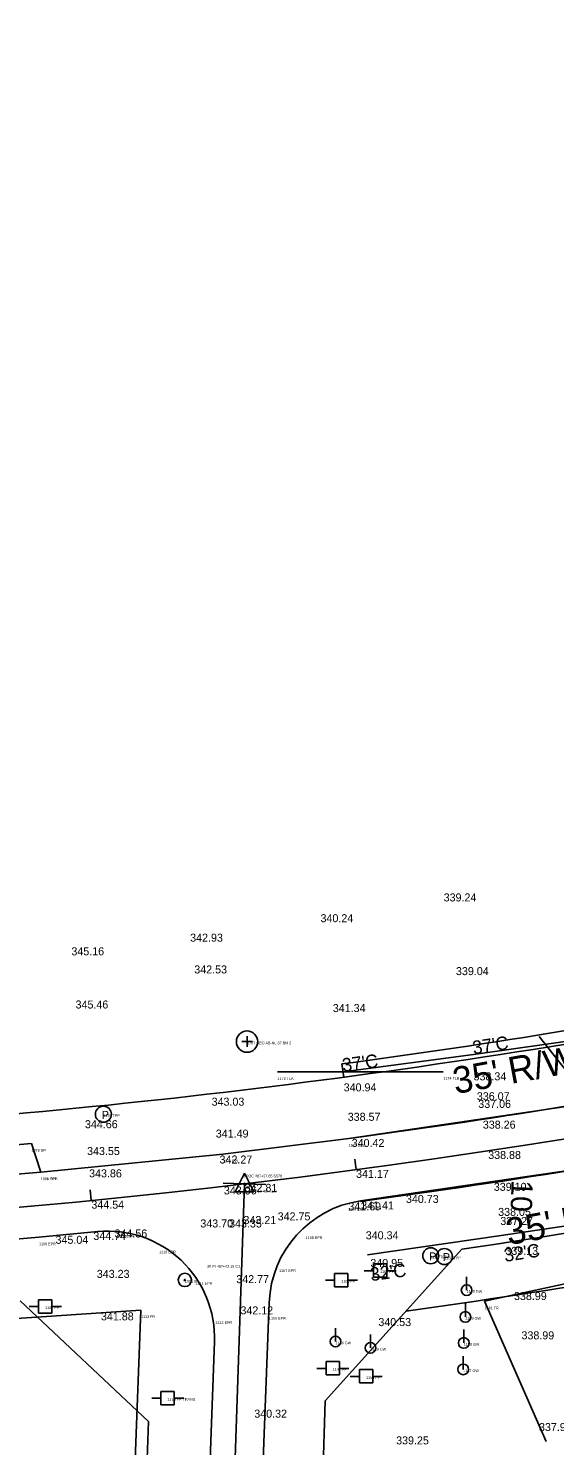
# Model space of a CAD drawing. Extents: x 49683 to 58852, y 49525 to 54803.
# Drawn here: x 50899 to 51097, y 49882 to 50413 of the extents above; entities that cross this region are included whole.
import ezdxf

# ---------------------------------------------------------------- set-up
doc = ezdxf.new("R2010")
doc.units = 0
for name, color, linetype in [('Level 1', 7, 'Continuous'), ('Level 11', 7, 'Continuous'), ('Level 12', 7, 'Continuous'), ('Level 13', 7, 'Continuous'), ('Level 18', 7, 'Continuous'), ('Level 20', 7, 'Continuous'), ('Level 21', 7, 'Continuous'), ('Level 25', 7, 'Continuous'), ('Level 3', 7, 'Continuous'), ('Level 32', 7, 'Continuous'), ('Level 33', 7, 'Continuous'), ('Level 34', 7, 'Continuous'), ('Level 48', 7, 'Continuous'), ('Level 51', 7, 'Continuous'), ('Level 53', 7, 'Continuous'), ('Level 58', 7, 'Continuous'), ('Level 59', 7, 'Continuous'), ('Level 61', 7, 'Continuous'), ('Level 62', 7, 'Continuous'), ('Level 8', 7, 'Continuous'), ('Level 9', 7, 'Continuous')]:
    doc.layers.add(name, color=color, linetype=linetype)

# ---------------------------------------------------------------- blocks, each defined once
blk = doc.blocks.new('PI')
at = {"layer": 'Level 1'}
for p, q in [((0, 4), (-3.5, -3)), ((0, 4), (3.5, -3)), ((-3.5, -3), (3.5, -3))]:
    blk.add_line(p, q, dxfattribs=at)
blk.add_circle((0, 0), 0.25, dxfattribs=at)
blk = doc.blocks.new('PP')
at = {"layer": 'Level 9'}
for p, q in [((2.53, 2.45), (-2.47, 2.45)), ((-2.47, 2.45), (-2.47, -2.55)), ((2.53, -2.55), (2.53, 2.45)), ((-5.91, -0.11), (-2.44, -0.11)), ((-2.47, -2.55), (2.53, -2.55)), ((2.45, -0.11), (6.09, -0.11))]:
    blk.add_line(p, q, dxfattribs=at)
blk = doc.blocks.new('GW')
at = {"layer": 'Level 9'}
blk.add_line((0, 0), (0, 5), dxfattribs=at)
blk.add_circle((0, 0), 2, dxfattribs=at)
blk = doc.blocks.new('TPP')
at = {"layer": 'Level 9'}
blk.add_circle((0, 0), 3, dxfattribs=at)
blk.add_text('P', height=3, dxfattribs=at).set_placement((-0.59, -1.73))
blk = doc.blocks.new('IP')
at = {"layer": 'Level 12'}
for radius in [2.5, 0.25]:
    blk.add_circle((0, 0), radius, dxfattribs=at)
blk = doc.blocks.new('GEO')
at = {"layer": 'Level 12'}
for p, q in [((2, 0), (-2, 0)), ((0, -2), (0, 2))]:
    blk.add_line(p, q, dxfattribs=at)
blk.add_circle((0, 0), 4, dxfattribs=at)

msp = doc.modelspace()

# ---------------------------------------------------------------- linework, layer by layer
at = {"layer": 'Level 1'}
for p, q in [((51022.26, 49985.1), (51021.73, 49989.07)), ((50922.94, 49973.54), (50922.55, 49977.52)), ((50980.44, 49979.81), (50970.24, 49679.98)), ((50972.45, 49980.08), (50980.44, 49979.81)), ((50980.44, 49979.81), (50988.44, 49979.53))]:
    msp.add_line(p, q, dxfattribs=at)
msp.add_arc((50641.56, 52824.47), 2864.78, 268.37962, 311.63333, dxfattribs=at)
at = {"layer": 'Level 11'}
for p, q in [((50992.78, 50021.8), (51054.93, 50021.86)), ((51070.44, 49935.78), (51197.3, 49963.31)), ((51093.47, 49883.18), (51070.44, 49935.78))]:
    msp.add_line(p, q, dxfattribs=at)
at = {"layer": 'Level 13'}
for p, q in [((51061.93, 49955.32), (51010.7, 49898.53)), ((50944.39, 49890.76), (50896.33, 49935.91)), ((51003.22, 49678.86), (51010.7, 49898.53)), ((50938.94, 49730.56), (50944.39, 49890.76))]:
    msp.add_line(p, q, dxfattribs=at)
for radius, start in [(2829.79, 274.71289), (2899.79, 278.33537)]:
    msp.add_arc((50641.55, 52824.48), radius, start, 282.71776, dxfattribs=at)
at = {"layer": 'Level 18'}
for p, q in [((51066.27, 50028.35), (51115.16, 50035.22)), ((51017.34, 50021.8), (51066.27, 50028.35)), ((51076.58, 49960.44), (51126.61, 49967.81)), ((51026.53, 49953.25), (51076.58, 49960.44))]:
    msp.add_line(p, q, dxfattribs=at)
at = {"layer": 'Level 20'}
for radius in [2852.79, 2876.79]:
    msp.add_arc((50641.56, 52824.48), radius, 277.63669, 284.5124, dxfattribs=at)
at = {"layer": 'Level 3'}
for p, q in [((51019.47, 49996.76), (51109.95, 50010.17)), ((50972.31, 49990.88), (51019.47, 49996.76)), ((50904, 49984.2), (50972.31, 49990.88)), ((50834.92, 49978.18), (50904, 49984.2)), ((51023.87, 49973.41), (51114.81, 49986.7)), ((50903.34, 49959.81), (50925.36, 49961.9)), ((50836.42, 49953.95), (50903.34, 49959.81)), ((50985.31, 49820.35), (50989.68, 49935.35)), ((50969.12, 49920.58), (50965.38, 49820.53))]:
    msp.add_line(p, q, dxfattribs=at)
for centre, start, end in [((51029.65, 49933.83), 98.3136, 177.8243), ((50929.15, 49922.08), 357.8573, 95.4304)]:
    msp.add_arc(centre, 40, start, end, dxfattribs=at)
at = {"layer": 'Level 33'}
msp.add_line((51016.95, 50024.75), (51017.61, 50019.79), dxfattribs=at)
for centre, radius, start, end in [((50641.56, 52824.47), 2824.78, 277.63672, 284.51288), ((50641.56, 52824.48), 2919.79, 277.86343, 284.5124)]:
    msp.add_arc(centre, radius, start, end, dxfattribs=at)
at = {"layer": 'Level 34'}
msp.add_line((51090.91, 50035.07), (51104.54, 50017.8), dxfattribs=at)
at = {"layer": 'Level 8'}
for p, q in [((50875.83, 49992.8), (50900.54, 49994.88)), ((50900.54, 49994.88), (50904, 49984.2)), ((50747.24, 49919.1), (50941.57, 49932.52)), ((50941.57, 49932.52), (50934.14, 49742.39))]:
    msp.add_line(p, q, dxfattribs=at)

# ---------------------------------------------------------------- block references
at = {"layer": 'Level 1'}
msp.add_blockref('PI', (50980.44, 49979.81), dxfattribs=at)
at = {"layer": 'Level 12'}
for name, p in [('GEO', (50981.38, 50033.12)), ('IP', (50958.03, 49943.78))]:
    msp.add_blockref(name, p, dxfattribs=at)
at = {"layer": 'Level 9'}
for name, p in [('TPP', (50927.48, 50005.9)), ('TPP', (51050.24, 49952.85)), ('TPP', (51055.37, 49952.58)), ('PP', (51016.68, 49943.82)), ('PP', (51031.23, 49947.38)), ('GW', (51063.7, 49939.98)), ('PP', (50905.64, 49933.91)), ('GW', (51063.22, 49929.92)), ('GW', (51014.53, 49920.71)), ('GW', (51027.66, 49918.34)), ('GW', (51062.61, 49920.17)), ('PP', (51013.46, 49910.75)), ('GW', (51062.42, 49910.28)), ('PP', (51025.99, 49907.72)), ('PP', (50951.52, 49899.57))]:
    msp.add_blockref(name, p, dxfattribs=at)

# ---------------------------------------------------------------- texts
at = {"layer": 'Level 21'}
msp.add_text('10', height=8, rotation=268.051, dxfattribs=at).set_placement((51080.55, 49981.31))
at = {"layer": 'Level 25'}
for rotation, p in [(10.421, (51059.51, 50013.42)), (10.6057, (51079.43, 49956.79))]:
    msp.add_text("35' R/W FILE # 408-B", height=10, rotation=rotation, dxfattribs=at).set_placement(p)
at = {"layer": 'Level 32'}
for s, p in [('339.24', (51055.08, 50085.68)), ('340.24', (51008.91, 50077.89)), ('342.93', (50960.03, 50070.59)), ('345.16', (50915.5, 50065.48)), ('342.53', (50961.58, 50058.69)), ('339.04', (51059.69, 50058.06)), ('345.46', (50917.07, 50045.54)), ('341.34', (51013.52, 50044.21)), ('338.34', (51066.28, 50018.61)), ('340.94', (51017.59, 50014.48)), ('336.07', (51067.52, 50011.15)), ('343.03', (50968.07, 50009.11)), ('337.06', (51068.05, 50008.28)), ('344.66', (50920.59, 50000.68)), ('338.57', (51019.11, 50003.45)), ('338.26', (51069.76, 50000.51)), ('341.49', (50969.64, 49997.16)), ('343.55', (50921.38, 49990.61)), ('340.42', (51020.59, 49993.66)), ('342.27', (50971.05, 49987.44)), ('338.88', (51071.78, 49989.14)), ('343.86', (50922.14, 49982.24)), ('341.17', (51022.24, 49982.06)), ('343.06', (50972.67, 49975.85)), ('342.81', (50980.44, 49976.81)), ('339.10', (51073.87, 49977.2)), ('344.54', (50922.99, 49970.51)), ('341.69', (51019.34, 49969.86)), ('341.41', (51024.17, 49970.24)), ('340.73', (51040.93, 49972.66)), ('343.70', (50963.85, 49963.47)), ('343.35', (50974.64, 49963.46)), ('343.21', (50980.03, 49964.75)), ('342.75', (50992.84, 49966.12)), ('338.05', (51075.51, 49967.8)), ('337.27', (51076.31, 49964.4)), ('344.74', (50923.73, 49958.78)), ('344.56', (50931.67, 49959.72)), ('340.34', (51025.87, 49959.04)), ('345.04', (50909.55, 49957.35)), ('339.13', (51078.22, 49953.2)), ('340.95', (51027.59, 49948.67)), ('343.23', (50925.03, 49944.57)), ('342.77', (50977.33, 49942.59)), ('338.99', (51081.45, 49936.26)), ('341.88', (50926.58, 49928.64)), ('342.12', (50978.87, 49930.88)), ('340.53', (51030.6, 49926.5)), ('338.99', (51084.26, 49921.53)), ('340.32', (50984.07, 49892.18)), ('337.99', (51090.82, 49887.15)), ('339.25', (51037.25, 49882.15))]:
    msp.add_text(s, height=3, dxfattribs=at).set_placement(p)
at = {"layer": 'Level 48'}
for s, rotation, p in [("37'C", 8.6367, (51066.27, 50028.35)), ("37'C", 7.6367, (51017.34, 50021.8)), ("32'C", 8.6367, (51078.08, 49950.55)), ("32'C", 7.6367, (51027.86, 49943.34))]:
    msp.add_text(s, height=5, rotation=rotation, dxfattribs=at).set_placement(p)
at = {"layer": 'Level 51'}
for s, p in [('3 POC 487+57.85 S576', (50979.8, 49982.24)), ('35 PI 10+00 SEC', (50981.8, 49976.57)), ('20 PI 487+43.15 C1', (50966.39, 49948.36))]:
    msp.add_text(s, height=1, dxfattribs=at).set_placement(p)
at = {"layer": 'Level 53'}
for s, p in [('1173 EPL', (51019.47, 49993.76)), ('1171 EPL', (50972.31, 49987.88)), ('1081 EPL', (50904, 49981.2)), ('1169 EPR', (51019.22, 49969.73)), ('1109 EPR', (50932.71, 49959.6)), ('1108 EPR', (50903.34, 49956.81)), ('1168 EPR', (51003.29, 49959.15)), ('1110 EPR', (50948.37, 49953.75)), ('1167 EPR', (50993.36, 49946.81)), ('1111 EPR', (50962, 49942.08)), ('1166 EPR', (50989.55, 49928.95)), ('1112 EPR', (50969.48, 49927.29))]:
    msp.add_text(s, height=1, dxfattribs=at).set_placement(p)
at = {"layer": 'Level 58'}
for s, p in [('1079 DP', (50900.54, 49991.88)), ('1080 DPB', (50904, 49981.2)), ('1113 FR', (50941.57, 49929.52))]:
    msp.add_text(s, height=1, dxfattribs=at).set_placement(p)
at = {"layer": 'Level 59'}
for s, p in [('1170 TPP', (50927.48, 50004.9)), ('1163 TPP', (51050.24, 49951.85)), ('1162 TPP', (51055.37, 49951.58)), ('1164 PP', (51031.23, 49946.38)), ('1165 PP', (51016.68, 49942.82)), ('1160 GW', (51063.7, 49938.98)), ('1107 PP', (50905.64, 49932.91)), ('1159 GW', (51063.22, 49928.92)), ('1148 GW', (51014.53, 49919.71)), ('1149 GW', (51027.66, 49917.34)), ('1158 GW', (51062.61, 49919.17)), ('1147 PP', (51013.46, 49909.75)), ('1150 PP', (51025.99, 49906.72)), ('1157 GW', (51062.42, 49909.28)), ('1114 PP TRANS', (50951.52, 49898.57))]:
    msp.add_text(s, height=1, dxfattribs=at).set_placement(p)
at = {"layer": 'Level 61'}
for s, p in [('1172 TLA', (50992.78, 50018.8)), ('1174 TLB', (51054.93, 50018.86)), ('1161 TR', (51070.44, 49932.78))]:
    msp.add_text(s, height=1, dxfattribs=at).set_placement(p)
at = {"layer": 'Level 62'}
for s, p in [('1707 GEO AB-NL-37 BM 2 ', (50981.38, 50032.12)), ('1001 IP', (50958.03, 49942.78))]:
    msp.add_text(s, height=1, dxfattribs=at).set_placement(p)

doc.saveas('drawing.dxf')
